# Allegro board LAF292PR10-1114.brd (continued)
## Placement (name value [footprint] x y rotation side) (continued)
PR612  1.91K_0402_1%  [R_0402]  67.17 78.74 0 top
PR613  86.6K_0402_1%  [R_0402]  69.77 78.62 90 top
PR614  0_0402_5%  [R0402_0OHM]  67.18 79.62 0 top
PR615  0_0402_5%  [R_0402]  75.63 81.16 90 bottom
PR616  0_0402_5%  [R0402_0OHM]  67.18 80.5 0 top
PR617  4.3K_0402_1%  [R_0402]  69.94 82.06 270 top
PR618  49.9_0402_1%  [R_0402]  67.19 78.26 0 bottom
PR619  2.2_0603_5%  [R_0603]  88.63 55.37 270 top
PR620  0_0402_5%  [R0402_0OHM]  68.61 82.07 270 bottom
PR621  316_0402_1%  [R_0402]  70.83 82.07 270 top
PR622  1.5K_0402_1%  [R_0402]  71.23 82.07 270 bottom
PR623  2K_0402_1%  [R_0402]  70.35 82.07 270 bottom
PR624  3.65K_0603_1%  [R_0603]  97.72 55.03 0 top
PR625  0_0402_5%  [R0402_0OHM]  67.19 77.38 0 bottom
PR626  10_0402_1%  [R_0402]  67.2 76.51 0 bottom
PR627  4.7_1206_5%  [R_1206]  90.34 54.63 0 top
PR628  4.99K_0402_1%  [R_0402]  99.6 77.51 270 top
PR629  86.6K_0402_1%  [R_0402]  74.45 78.23 0 top
PR630  2.49K_0402_1%  [R_0402]  73.05 72.37 270 top
PR631  27.4K_0402_1%  [R_0402]  68.59 82.92 0 bottom
PR632  1K_0402_1%  [R_0402]  73.57 82.96 180 top
PR633  11K_0402_1%  [R_0402]  72.57 81.17 90 top
PR634  0_0402_5%  [R_0402]  74.74 81.17 90 bottom
PR635  10K_0402_1%  [R_0402]  76.8 79.01 270 bottom
PR636  665_0402_1%  [R_0402]  68.85 72.36 270 bottom
PR638  360_0402_1%  [R_0402]  72.98 82.07 270 bottom
PR639  3.09K_0402_1%  [R_0402]  77.77 77.21 180 bottom
PR640  357_0402_1%  [R_0402]  77 74.13 0 bottom
PR641  1K_0402_1%  [R_0402]  68.11 70.57 0 bottom
PR642  2.61K_0402_1%  [R_0402]  98.25 54.03 0 bottom
PR643  11K_0402_1%  [R_0402]  71.5 71.45 90 bottom
PR644  1K_0402_1%  [R_0402]  77 73.24 0 bottom
PR645  316_0402_1%  [R_0402]  77.67 75.97 180 top
PR646  316_0402_1%  [R_0402]  74.13 72.07 270 bottom
PR647  27.4K_0402_1%  [R_0402]  77.7 79.88 180 bottom
PR648  1.91K_0402_1%  [R_0402]  77.97 76.29 180 bottom
PR649  1.62K_0402_1%  [R_0402]  73.24 72.37 270 bottom
PR650  2K_0402_1%  [R_0402]  76.76 76.85 0 top
PR651  113K_0402_1%  [R_0402]  73.91 72.37 270 top
PR652  2K_0402_1%  [R_0402]  75.02 72.07 270 bottom
PR653  20M_0402_5%  [R_0402]  74.44 74.74 0 top
PR656  11K_0402_1%  [R_0402]  76.77 75.08 0 top
PR657  4.42K_0402_1%  [R_0402]  100.18 62.66 0 top
PR658  20M_0402_5%  [R_0402]  73.31 78.71 90 top
PR659  0_0402_5%  [R0402_0OHM]  86.34 71.55 0 bottom
PR660  3.9_0603_1%  [R_0603]  85.91 74.35 359.6 bottom
PR661  3.65K_0603_1%  [R_0603]  99.01 61.47 90 top
PR663  4.7_1206_5%  [R_1206]  93.06 82.38 180 bottom
PR664  0_0402_5%  [R0402_0OHM]  76.18 71.52 270 bottom
PR665  3.9_0603_1%  [R_0603]  90.3 54.9 90 bottom
PR666  10_0402_1%  [R_0402]  99.61 74.82 90 top
PR667  3.65K_0603_1%  [R_0603]  99.76 78.39 90 top
PR668  100K_0603_1%  [R_0603]  100.98 79.79 270 top
PR669  4.7_1206_5%  [R_1206]  98.37 59.55 180 top
PR670  100K_0402_1%  [R_0402]  100.48 77.51 270 top
PR671  0_0402_5%  [R_0402]  86.23 62.85 0 top
PR672  3.9_0603_1%  [R_0603]  84.99 61.65 90 bottom
PR673  10_0402_1%  [R_0402]  94.04 68.91 90 top
PR674  3.65K_0603_1%  [R_0603]  91.8 70.37 270 top
PR675  100K_0603_1%  [R_0603]  93 68.97 90 top
PR676  4.7_1206_5%  [R_1206]  84.66 70.98 180 bottom
PR677  100K_0402_1%  [R_0402]  93.96 71.29 180 top
PR678  100_0402_1%  [R_0402]  67.18 77.85 0 top
PR679  0_0402_5%  [R0402_0OHM]  85.51 50.98 180 bottom
PR682  -  [SOLDER_PREFORMS_0603]  130.43 69.62 180 top
PR683  -  [SOLDER_PREFORMS_0603]  126.46 74.13 0 top
PR684  -  [SOLDER_PREFORMS_0603]  131.03 74.15 180 top
PR686  10K_0402_1%  [R_0402]  88.99 71.94 180 top
PR687  0_0402_5%  [R0402_0OHM]  86.33 70.67 0 bottom
PR688  1_0603_5%  [R_0603]  84.86 72.73 0 bottom
PR689  10K_0402_1%  [R_0402]  89.57 64.91 270 bottom
PR691  1_0603_5%  [R_0603]  89.73 64.35 180 top
PR692  0_0402_5%  [R_0402]  86.23 61.97 0 top
PR901  0.01_1206_1%  [R_1206_4P-D]  60.01 60.44 270 bottom
PR909  2_0603_1%  [R_0603]  49.76 33.72 0 top
PR910  2_0603_1%  [R_0603]  49.76 34.92 0 top
PR914  4.7_0603_5%  [R_0603]  51.8 37.02 180 top
PR915  4.7_0603_5%  [R_0603]  50.78 40.88 270 top
PR916  1_0805_5%  [R_0805]  63.42 32.21 270 top
PR917  0.005_1206_1%  [R_1206_4P-D]  61.54 56.63 180 top
PR918  100K_0402_1%  [R_0402]  54.19 32.16 90 top
PR919  0_0402_5%  [R_0402]  55.08 32.17 90 top
PR920  0_0402_5%  [R0402_0OHM]  56.13 31.89 90 top
PR921  4.7_0603_5%  [R_0603]  53.84 40.58 90 top
PR922  0_0402_5%  [R0402_0OHM]  57.02 31.89 90 top
PR923  4.7_1206_5%  [R_1206]  54.96 51.67 180 top
PR924  4.7_1206_5%  [R_1206]  65.69 47.85 0 top
PR925  154K_0402_1%  [R_0402]  53.28 30.39 90 top
PR926  0_0402_5%  [R0402_0OHM]  57.9 31.89 90 top
PR927  1M_0402_1%  [R_0402]  49.04 31.3 270 top
PR928  0_0402_5%  [R0402_0OHM]  54.2 31.33 270 top
PR929  0_0402_5%  [R0402_0OHM]  56.13 40.56 90 top
PR930  100K_0402_1%  [R_0402]  58.94 32.13 270 top
PR931  100K_0402_1%  [R_0402]  59.85 33.02 180 top
PR932  105K_0402_1%  [R_0402]  58.91 35.46 0 top
PR933  100K_0402_1%  [R_0402]  59.82 34.56 180 top
PR934  0_0402_5%  [R0402_0OHM]  59.35 36.52 90 top
PR935  0_0402_5%  [R0402_0OHM]  63.11 41.23 180 top
PR936  0_0402_5%  [R0402_0OHM]  58.89 38.57 0 top
PR937  1_0603_1%  [R_0603]  57.54 42.93 90 top
PR938  1_0603_1%  [R_0603]  58.74 42.93 90 top
PR939  0_0402_5%  [R0402_0OHM]  68.84 39.55 180 top
PR940  100_0402_5%  [R_0402]  60.51 41.23 180 top
PR941  0_0402_5%  [R0402_0OHM]  67.92 36.05 0 top
PR942  0_0402_5%  [R0402_0OHM]  65.13 40.22 270 top
PR943  0_0603_5%  [R_0603]  51.5 44.4 270 top
PR944  442K_0402_1%  [R_0402]  52.62 43.92 270 top
PR945  100K_0402_5%  [R_0402]  53.55 43.01 90 top
PR946  0_0402_5%  [R0402_0OHM]  63.16 34.71 270 top
PR947  0_0402_5%  [R0402_0OHM]  63.99 41.13 270 top
PR948  16.5K_0402_1%  [R_0402]  58.89 39.46 0 top
PR950  0_0402_5%  [R_0402]  64.05 34.71 270 top
PR951  0_0402_5%  [R0402_0OHM]  71.71 83.83 180 bottom
PR953  100K_0402_1%  [R_0402]  62.27 33.79 90 top
PR960  0_0402_5%  [R0402_0OHM]  56.72 30.98 180 top
PR961  100K_0402_1%  [R_0402]  66.08 39.31 90 top
PR1201  1M_0402_1%  [R_0402]  52.95 86.45 90 top
PR1202  300K_0402_5%  [R_0402]  41.44 72.98 0 top
PR1203  499K_0402_1%  [R_0402]  52.57 83.65 180 bottom
PR1204  499K_0402_1%  [R_0402]  48.43 75.65 90 top
PR1205  100K_0402_5%  [R_0402]  62.58 81.5 180 top
PR1206  1M_0402_5%  [R_0402]  52.57 87.33 0 bottom
PR1207  100K_0402_5%  [R_0402]  39.67 72.98 0 top
PR1208  0_0402_5%  [R0402_0OHM]  63.52 81.48 0 top
PR1209  49.9K_0402_1%  [R_0402]  57.42 85.57 270 top
PR1210  0_0402_5%  [R0402_0OHM]  61.22 77.78 90 top
PR1211  100K_0402_5%  [R_0402]  50.72 86.7 0 bottom
PR1212  49.9K_0402_1%  [R_0402]  61.12 83.53 90 top
PR1213  100K_0402_5%  [R_0402]  49.5 90.28 180 bottom
PR1214  0_0402_5%  [R0402_0OHM]  60.37 82.58 270 top
PR1215  499K_0402_1%  [R_0402]  45.33 87.08 180 top
PR1216  221K_0402_1%  [R_0402]  44.42 89.75 0 top
PR1217  47K_0402_1%  [R_0402]  47.87 90.76 180 top
PR1218  1.8M_0402_1%  [R_0402]  48.74 85.54 90 bottom
PR1219  0_0402_5%  [R0402_0OHM]  64.46 85.41 270 top
PR1220  100K_0402_5%  [R_0402]  58.58 81.76 0 top
PR1221  0_0402_5%  [R0402_0OHM]  58.46 86.46 180 top
PR1222  0_0402_5%  [R0402_0OHM]  64.48 82.69 90 top
PR1223  0_0402_5%  [R0402_0OHM]  46.96 91.65 0 top
PR1224  100K_0402_5%  [R_0402]  60.21 86.44 180 top
PR1225  200K_0402_1%  [R_0402]  44.42 87.97 0 top
PR1226  0_0402_5%  [R0402_0OHM]  57.51 88.75 180 bottom
PR1227  200K_0402_1%  [R_0402]  45.33 91.53 180 top
PR1228  100K_0402_5%  [R_0402]  55.21 85.18 0 bottom
PR1229  100K_0402_5%  [R_0402]  58.84 88.73 0 bottom
PR1230  0_0402_5%  [R0402_0OHM]  38.67 87.36 270 top
PR1231  10K_0402_5%  [R_0402]  40.41 85.56 0 top
PR1232  0_0402_5%  [R0402_0OHM]  39.56 85.55 180 top
PR1233  0_0402_5%  [R0402_0OHM]  54.48 86.88 90 bottom
PR1234  1M_0402_1%  [R_0402]  40.3 51.77 0 top
PR1235  300K_0402_5%  [R_0402]  43.4 57.17 180 top
PR1236  1M_0402_5%  [R_0402]  41.06 45.47 90 top
PR1237  499K_0402_1%  [R_0402]  41.54 44.33 270 top
PR1238  499K_0402_1%  [R_0402]  49.07 49.23 90 top
PR1239  100K_0402_5%  [R_0402]  38.28 41.28 90 top
PR1240  100K_0402_5%  [R_0402]  44.26 58 270 top
PR1241  0_0402_5%  [R0402_0OHM]  38.33 40.45 270 top
PR1242  100K_0402_5%  [R_0402]  48.23 46.95 0 top
PR1243  0_0402_5%  [R0402_0OHM]  34.81 40.49 90 top
PR1244  49.9K_0402_1%  [R_0402]  42.41 37.11 90 top
PR1245  0_0402_5%  [R0402_0OHM]  42.89 32.95 0 top
PR1246  49.9K_0402_1%  [R_0402]  45.88 36.69 0 top
PR1247  0_0402_5%  [R0402_0OHM]  42.1 32.04 270 top
PR1248  0_0402_5%  [R0402_0OHM]  45.07 34 90 top
PR1249  100K_0402_5%  [R_0402]  49.7 43.02 180 top
PR1250  100K_0402_5%  [R_0402]  43.22 34.88 0 top
PR1251  0_0402_5%  [R0402_0OHM]  37.58 32.98 180 top
PR1252  499K_0402_1%  [R_0402]  33.17 34.08 90 top
PR1253  221K_0402_1%  [R_0402]  39.36 32.98 180 top
PR1254  47K_0402_1%  [R_0402]  36.98 38.71 180 top
PR1255  0_0402_5%  [R0402_0OHM]  43.16 38.88 180 top
PR1256  1.8M_0402_1%  [R_0402]  34.13 39.01 0 top
PR1257  100K_0402_5%  [R_0402]  44.94 38.86 180 top
PR1258  100K_0402_5%  [R_0402]  41.19 31.12 90 top
PR1259  0_0402_5%  [R0402_0OHM]  35.04 37.07 270 top
PR1260  100K_0402_5%  [R_0402]  35.73 31.89 90 top
PR1261  200K_0402_1%  [R_0402]  34.09 35.02 270 top
PR1262  200K_0402_1%  [R_0402]  36.95 34.12 180 top
PR1263  100K_0402_5%  [R_0402]  65.19 83.35 270 bottom
PR1264  100K_0402_5%  [R_0402]  65.24 87.72 0 bottom
PR1265  0_0402_5%  [R0402_0OHM]  34.84 31.89 90 top
PR1266  0_0402_5%  [R0402_0OHM]  43.48 33.49 0 bottom
PR1267  100K_0402_5%  [R_0402]  69.56 86.85 90 bottom
PR1268  100K_0402_5%  [R_0402]  74.8 83.52 180 bottom
PR1269  0_0402_5%  [R0402_0OHM]  43.48 32.6 0 bottom
PR1270  10K_0402_5%  [R_0402]  42.08 33.49 180 bottom
PR1271  100K_0402_5%  [R_0402]  67.15 87.72 0 bottom
PR1272  100K_0402_5%  [R_0402]  74.13 87.59 0 bottom
PR1273  0_0402_5%  [R0402_0OHM]  66.08 82.64 90 bottom
PR1274  0_0402_5%  [R0402_0OHM]  76.37 84.97 90 bottom
PR1275  0_0402_5%  [R0402_0OHM]  64.18 88.55 270 bottom
PR1276  0_0402_5%  [R0402_0OHM]  64.3 82.43 90 bottom
PR1277  300K_0402_5%  [R_0402]  46.02 84.12 270 bottom
PR1278  100K_0402_5%  [R_0402]  38.8 82.31 90 top
PR1279  100K_0402_5%  [R_0402]  46.02 82.37 270 bottom
PR1280  300K_0402_5%  [R_0402]  46.82 42.62 270 top
PR1281  100K_0402_5%  [R_0402]  47.64 34.92 0 top
PR1282  100K_0402_5%  [R_0402]  46.82 40.79 270 top
PR1283  0_0402_5%  [R_0402]  45.59 32.98 180 top
PR1284  0_0402_5%  [R_0402]  66.29 85.43 180 top
PR1285  1M_0402_5%  [R_0402]  42.72 84.29 270 top
PR1286  1M_0402_5%  [R_0402]  41.11 32.98 0 top
PR1287  10K_0402_5%  [R_0402]  51.68 85.81 180 bottom
PR1288  10K_0402_5%  [R_0402]  43.98 37.8 180 bottom
PR1289  0_0402_5%  [R_0402]  69.56 85.02 90 bottom
PR1290  0_0402_5%  [R_0402]  76.57 83.52 180 bottom
PR1291  100K_0402_5%  [R_0402]  72.23 87.72 0 bottom
PR1292  0_0402_5%  [R0402_0OHM]  71.37 87.72 180 bottom
PR1293  0_0402_5%  [R_0402]  69.33 83.92 180 bottom
PR1294  0_0402_5%  [R_0402]  77.39 85.89 270 bottom
PR1295  0_0402_5%  [R0402_0OHM]  47.86 91.3 180 bottom
PR1296  0_0402_5%  [R0402_0OHM]  49.26 42.13 180 top
PR1298  10K_0402_1%  [R_0402]  94.26 57.92 270 bottom
PR1299  0_0402_5%  [R0402_0OHM]  77.06 71.52 270 bottom
PR1300  1_0603_5%  [R_0603]  91.32 64.74 270 top
PRP1  100_0804_8P4R_5%  [RP_0804_8P4R]  67.83 44.07 270 top
PT1  PAD~D  [TPC12]  38.35 84.6 0 top
PT2  PAD~D  [TPC12]  38.33 41.66 180 bottom
PU100  -  [SY8288BRAC_QFN20_3X3]  72.53 43.25 0 bottom
PU102  SYV828CRAC QFN 20P PWM  [SY8288CRAC_QFN20_3X3]  50.69 70.18 0 bottom
PU200  -  [SY8210AQVC_QFN19_4X3]  85.79 44.92 180 bottom
PU301  SY8286RAC_QFN20_3X3  [SY8288RAC_QFN20_3X3]  60.98 71.58 0 bottom
PU401  -  [TPS62134CRGT_QFN16_3X3]  178.86 27.77 180 top
PU402  TPS62134DRGT_QFN16_3X3  [TPS62134ARGT_QFN16_3X3]  165.55 31.1 90 bottom
PU501  -  [RT8097ALGE_SOT23-6]  211.79 28.33 90 top
PU503  AP7361C-FGE-7-01_U-DFN3030-8_3X3  [AP7361C-FGE-7_U-DFN3030-8_3X3]  78.65 51.48 0 top
PU602  ISL95857AHRTZ-T TQFN 40P PWM  [ISL62883CHRTZ-T_TQFN40_5X5-S]  70.49 79 0 bottom
PU610  FDMF3035_PQFN31_5X5  [NCP302045MNTWG_PQFN33_5X5]  88.56 72.24 90 bottom
PU612  FDMF3035_PQFN31_5X5  [NCP302045MNTWG_PQFN33_5X5]  92.31 57.58 180 bottom
PU613  FDMF3035_PQFN31_5X5  [NCP302045MNTWG_PQFN33_5X5]  87.65 64.33 180 bottom
PU614  ISL95808HRZ-TS2378_DFN8_2X2  [ISL95808HRZ-TS2378_DFN8_2X2-S]  89.02 50.95 270 bottom
PU901  ISL9538HRTZ-T TQFN 32P PWM  [ISL88738HRTZ-T_TQFN32_4X4]  56.94 38.59 270 top
PU903  MC74VHC1G08DFT2G SC70 5P AND  [SN74AHC1G08DCKR_SC70-5]  65.36 37.94 180 top
PU1201  -  [LM393DGKR_VSSOP8]  44.87 90.89 180 bottom
PU1202  MC74VHC1G08DFT2G SC70 5P AND  [SN74AHC1G08DCKR_SC70-5]  65.64 84.25 270 top
PU1203  MC74VHC1G08DFT2G SC70 5P AND  [SN74AHC1G08DCKR_SC70-5]  43.25 31.79 270 top
Q1  -  [L2N7002WT1G_SC-70-3]  241.6 74.25 180 top
QC2  -  [DMN65D8LDW-7_SOT363-6]  151.87 76.43 270 top
QC3  S TR BSS138W 1N SOT-323-3  [L2N7002WT1G_SC-70-3]  248.71 86.51 0 top
QC4  DMN63D8LDW-7_SOT363-6  [DMN65D8LDW-7_SOT363-6]  181.64 39.1 180 bottom
QC6  -  [L2N7002WT1G_SC-70-3]  20.24 85.5 0 bottom
QC7  -  [LP2301ALT1G_SOT23-3]  30.29 82.25 90 top
QE2  -  [DMN65D8LDW-7_SOT363-6]  249.95 69.65 0 top
QE3  LMBT3904WT1G SC70-3  [MMBT3904WT1G_SC70-3]  121.27 65.36 270 top
QE4  LMBT3904WT1G SC70-3  [MMBT3904WT1G_SC70-3]  255.31 47.64 180 top
QE5  LMBT3904WT1G SC70-3  [MMBT3904WT1G_SC70-3]  43.48 65.94 180 bottom
QE6  LMBT3904WT1G SC70-3  [MMBT3904WT1G_SC70-3]  80.07 51.25 90 bottom
QE7  LMBT3904WT1G SC70-3  [MMBT3904WT1G_SC70-3]  162.77 38.2 180 bottom
QE11  -  [L2N7002WT1G_SC-70-3]  252.77 47.64 0 top
QE12  -  [L2N7002WT1G_SC-70-3]  263.57 75.9 270 top
QE15  -  [LP2301ALT1G_SOT23-3]  266.87 84.03 90 top
QE17  -  [L2N7002WT1G_SC-70-3]  263.57 78.57 270 top
QR1  -  [L2N7002WT1G_SC-70-3]  277.92 61.81 180 top
QT1  -  [DMN66D0LDW-7_SOT363-6]  38.08 89.73 90 top
QT2  -  [DMN66D0LDW-7_SOT363-6]  26.02 37.44 270 top
QV1  -  [AO6405_TSOP6]  224.41 32.69 270 bottom
QV2  -  [L2N7002WT1G_SC-70-3]  228.01 30.69 270 bottom
QV3  -  [DMN65D8LDW-7_SOT363-6]  17.89 50.98 90 bottom
QV4  -  [L2N7002WT1G_SC-70-3]  14.33 37.78 180 bottom
QV5  -  [L2N7002WT1G_SC-70-3]  33.32 91.97 180 bottom
QV6  -  [L2N7002WT1G_SC-70-3]  14.9 54.63 0 top
QZ1  -  [LP2301ALT1G_SOT23-3]  227.4 34.17 90 bottom
QZ2  -  [DMN65D8LDW-7_SOT363-6]  256.33 87.46 90 top
QZ3  -  [DDTA114EUA-7-F_SOT323-3]  251.59 88.1 270 top
QZ4  -  [L2N7002WT1G_SC-70-3]  250.74 75.2 0 top
QZ10  -  [DMN65D8LDW-7_SOT363-6]  230.8 53.27 180 top
QZ13  -  [DMN65D8LDW-7_SOT363-6]  230.8 50.22 180 top
QZ14  -  [DMN65D8LDW-7_SOT363-6]  226.85 48.28 0 top
QZ15  S TR BSS138W 1N SOT-323-3  [L2N7002WT1G_SC-70-3]  236.58 31.84 270 bottom
RA3  0_0603_5%  [R0603_0OHM]  264.89 28.5 90 top
RA5  2.2K_0402_5%  [R_0402]  273.41 31.89 180 top
RA6  2.2K_0402_5%  [R_0402]  272.52 33.66 270 top
RA7  16.2_0402_1%  [R_0402]  272.5 30.94 0 top
RA8  16.2_0402_1%  [R_0402]  272.5 29.99 0 top
RA9  33_0402_5%  [R_0402]  261.05 32.93 0 top
RA12  1K_0402_5%  [R_0402]  275.1 36.66 0 top
RA13  1K_0402_5%  [R_0402]  275.1 35.77 0 top
RA14  22_0402_5%  [R_0402]  261.05 35.09 0 top
RA17  33_0402_5%  [R_0402]  261.97 34.22 180 top
RA18  10K_0402_5%  [R_0402]  259 40.39 90 top
RA35  0_0402_5%  [R0402_0OHM]  273.73 28.36 270 top
RA36  0_0402_5%  [R0402_0OHM]  275 28.36 270 top
RA37  0_0402_5%  [R0402_0OHM]  276.67 41.82 180 top
RA44  100K_0402_5%  [R_0402]  272.15 40.47 180 top
RA45  10K_0402_5%  [R_0402]  274.92 34.91 270 top
RA48  0_0402_5%  [R0402_0OHM]  257.4 39.46 0 top
RA50  0_0402_5%  [R_0402]  259.89 41.31 270 top
RA51  10K_0402_5%  [R_0402]  276.58 37.63 90 top
RA52  0_0402_5%  [R0402_0OHM]  274.81 30.94 0 top
RA53  0_0402_5%  [R0402_0OHM]  274.81 29.99 0 top
RA54  0_0402_5%  [R_0402]  264.38 41.13 90 top
RA55  0_0402_5%  [R0402_0OHM]  263.43 41.13 90 top
RA58  10K_0402_5%  [R_0402]  296.03 20.41 180 top
RA59  100K_0402_1%  [R_0402]  260.77 42 270 top
RA60  200K_0402_1%  [R_0402]  261.66 41.08 90 top
RA61  100K_0402_5%  [R_0402]  262.54 41.98 270 top
RA62  100K_0402_5%  [R_0402]  261.05 35.89 0 top
RC1  100K_0402_5%  [R_0402]  150.03 75.27 270 top
RC2  24.9_0402_1%  [R_0402]  126.33 78.95 180 top
RC3  100_0402_1%  [R_0402]  149.52 78.77 270 top
RC4  200_0402_1%  [R_0402]  157.31 63.55 180 top
RC5  200_0402_1%  [R_0402]  146.4 62.95 0 top
RC6  80.6_0402_1%  [R_0402]  146.39 54.45 270 top
RC7  162_0402_1%  [R_0402]  147.92 53.12 270 top
RC10  1K_0402_1%  [R_0402]  165.06 91.6 270 top
RC11  1K_0402_1%  [R_0402]  162.14 58.63 180 bottom
RC12  1K_0402_5%  [R_0402]  163.28 74.25 0 top
RC14  1K_0402_5%  [R_0402]  160.9 75.8 0 top
RC15  1K_0402_5%  [R_0402]  162.57 71.33 0 top
RC16  15_0402_5%  [R_0402]  161.84 54.52 270 bottom
RC17  1K_0402_5%  [R_0402]  160.22 70.99 0 top
RC21  8.2K_0402_1%  [R_0402]  162.32 51.9 0 bottom
RC22  22_0402_5%  [R_0402]  163.67 53.93 0 bottom
RC23  2.2K_0402_5%  [R_0402]  155.54 71.26 0 top
RC25  4.7K_0402_5%  [R_0402]  157.32 71.28 270 top
RC27  8.2K_0402_5%  [R_0402]  163.67 52.79 0 bottom
RC28  33_0402_5%  [R_0402]  168.57 52.1 270 bottom
RC29  33_0402_5%  [R_0402]  177.35 60.52 90 top
RC30  1K_0402_5%  [R_0402]  178.48 56.55 270 top
RC31  1K_0402_5%  [R_0402]  176.7 56.55 270 top
RC32  0_0402_5%  [R_0402]  172.44 44.12 180 top
RC33  0_0402_5%  [R0402_0OHM]  172.44 45.2 180 top
RC34  0_0402_5%  [R0402_0OHM]  172.44 46.28 180 top
RC35  0_0402_5%  [R0402_0OHM]  172.44 47.36 180 top
RC36  0_0402_5%  [R0402_0OHM]  172.44 48.34 180 top
RC37  0_0402_5%  [R0402_0OHM]  180.26 59.24 90 bottom
RC38  0_0402_5%  [R0402_0OHM]  172.44 49.29 180 top
RC39  33_0402_5%  [R_0402]  180.26 57.49 90 bottom
RC40  0_0402_5%  [R0402_0OHM]  172.46 50.25 180 top
RC41  0_0402_5%  [R0402_0OHM]  172.43 52.33 270 top
RC42  0_0402_5%  [R_0402]  180.26 55.71 90 bottom
RC43  33_0402_5%  [R_0402]  181.65 54.44 180 bottom
RC44  113_0402_1%  [R_0402]  153.25 70.06 0 top
RC45  100_0402_1%  [R_0402]  153.74 78.02 90 top
RC46  1M_0402_1%  [R_0402]  131.61 90.51 180 bottom
RC47  10K_0402_5%  [R_0402]  158.95 52.56 180 top
RC48  1K_0402_5%  [R_0402]  152.36 51.22 270 bottom
RC50  10K_0201_1%  [R_0201]  151.26 65.57 0 top
RC51  10K_0402_5%  [R_0402]  155.36 62.87 90 top
RC52  2.7K_0402_1%  [R_0402]  142.77 73.87 0 top
RC54  10M_0402_5%  [R_0402]  159.73 62.77 180 top
RC56  20K_0402_5%  [R_0402]  152.62 51.57 90 top
RC57  20K_0402_5%  [R_0402]  154.9 54.44 270 top
RC59  10K_0402_5%  [R_0402]  161 51.93 270 top
RC60  0_0402_5%  [R_0402]  189.03 37.63 180 bottom
RC65  100K_0402_5%  [R_0402]  184.62 36.23 180 bottom
RC67  1K_0402_5%  [R_0402]  154.86 51.22 270 bottom
RC68  10K_0402_5%  [R_0402]  156.63 51.22 270 bottom
RC69  1M_0402_5%  [R_0402]  152.44 54.39 270 top
RC71  1K_0402_5%  [R_0402]  110.46 87.59 0 bottom
RC72  8.2K_0402_5%  [R_0402]  154.01 54.44 270 top
RC73  10K_0402_5%  [R_0402]  155.82 54.44 270 top
RC74  10K_0402_5%  [R_0402]  157.7 47.96 0 top
RC75  10K_0402_5%  [R_0402]  151.47 51.22 270 bottom
RC77  1K_0402_5%  [R_0402]  103.56 84.03 0 bottom
RC78  60.4_0402_1%  [R_0402]  110.53 86.65 270 bottom
RC79  49.9_0402_1%  [R_0402]  118.28 85.86 90 bottom
RC80  1K_0402_5%  [R_0402]  116.5 85.86 90 bottom
RC81  51_0402_5%  [R_0402]  120.57 87.77 90 bottom
RC82  100_0402_5%  [R_0402]  122.52 85.86 90 bottom
RC83  1K_0402_5%  [R_0402]  105.55 85.91 90 bottom
RC84  499_0402_1%  [R_0402]  106.44 86.83 270 bottom
RC86  51_0402_5%  [R_0402]  121.58 85.86 90 bottom
RC87  1K_0402_5%  [R_0402]  118.79 87.77 90 bottom
RC88  49.9_0402_1%  [R_0402]  149.06 53.12 270 top
RC89  49.9_0402_1%  [R_0402]  149.95 53.12 270 top
RC90  49.9_0402_1%  [R_0402]  117.34 76.8 180 top
RC91  49.9_0402_1%  [R_0402]  117.34 75.92 180 top
RC92  33_0402_5%  [R_0402]  146.6 52.03 90 bottom
RC93  33_0402_5%  [R_0402]  145.71 50 90 bottom
RC94  33_0402_5%  [R_0402]  149.27 50.25 180 top
RC95  33_0402_5%  [R_0402]  144.82 50 90 bottom
RC96  200_0402_1%  [R_0402]  152.11 70.82 180 top
RC109  1K_0402_5%  [R_0402]  103.75 82.24 270 bottom
RC110  10K_0402_1%  [R_0402]  102.77 86.63 180 bottom
RC112  10K_0402_1%  [R_0402]  106.23 84.17 180 bottom
RC113  10K_0402_1%  [R_0402]  104.69 85.94 180 bottom
RC114  49.9_0402_1%  [R_0402]  121.89 78.22 180 top
RC115  1.5K_0402_5%  [R_0402]  63.16 87.64 90 bottom
RC120  100K_0402_5%  [R_0402]  111.4 85.79 90 bottom
RC121  0_0402_5%  [R_0402]  71.72 92.08 270 bottom
RC122  0_0402_5%  [R_0402]  70.83 92.08 270 bottom
RC123  1K_0402_5%  [R_0402]  67.91 91.17 90 bottom
RC124  1K_0402_5%  [R_0402]  67.02 91.17 90 bottom
RC126  1K_0402_5%  [R_0402]  73.7 91.11 180 bottom
RC128  0_0402_5%  [R_0402]  60.29 91.1 90 bottom
RC129  0_0402_5%  [R_0402]  61.24 91.1 90 bottom
RC130  51_0402_5%  [R_0402]  119.68 87.77 90 bottom
RC131  51_0402_5%  [R_0402]  84.29 90.64 0 top
RC132  150_0402_5%  [R_0402]  72.79 92 0 bottom
RC133  1.5K_0402_5%  [R_0402]  59.34 91.1 90 bottom
RC134  51_0402_5%  [R_0402]  86.38 89.46 0 top
RC135  100_0402_5%  [R_0402]  86.38 87.56 0 top
RC136  51_0402_5%  [R_0402]  80.5 87.69 180 top
RC137  3K_0402_5%  [R_0402]  62.32 86.49 270 top
RC138  51_0402_5%  [R_0402]  75.21 91.95 270 bottom
RC139  51_0402_5%  [R_0402]  58.39 91.1 90 bottom
RC140  100_0402_1%  [R_0402]  139.15 85.43 90 bottom
RC141  100_0402_1%  [R_0402]  138.27 85.43 90 bottom
RC143  0_0603_5%  [R0603_0OHM]  135.89 87.61 180 top
RC152  56_0402_1%  [R_0402]  113.17 85.79 90 bottom
RC153  220_0402_5%  [R_0402]  114.06 85.79 90 bottom
RC157  100_0402_1%  [R_0402]  112.29 85.79 90 bottom
RC161  100_0402_1%  [R_0402]  114.39 76.46 90 top
RC163  100_0402_1%  [R_0402]  115.28 76.46 90 top
RC165  100_0402_1%  [R_0402]  141.18 65.48 180 top
RC166  100_0402_1%  [R_0402]  144.74 77.76 90 top
RC167  100_0402_1%  [R_0402]  142.04 65.33 90 top
RC168  100_0402_1%  [R_0402]  145.71 78.7 270 top
RC169  0_0603_5%  [R0603_0OHM]  153.5 87.7 180 top
RC170  0_0402_5%  [R0402_0OHM]  147.67 88.49 270 top
RC171  0_0402_5%  [R0402_0OHM]  137.88 88.32 270 top
RC173  0_0402_5%  [R0402_0OHM]  143.43 88.34 270 top
RC175  2.2K_0402_5%  [R_0402]  156.81 73.22 180 top
RC176  2.2K_0402_5%  [R_0402]  154.84 74.99 0 top
RC177  2.2K_0402_5%  [R_0402]  154.84 74.11 0 top
RC178  2.2K_0402_5%  [R_0402]  156.81 72.33 180 top
RC183  8.2K_0402_5%  [R_0402]  158.92 50.71 270 top
RC184  8.2K_0402_5%  [R_0402]  154.49 64.6 0 top
RC186  4.7K_0402_5%  [R_0402]  157.65 54.44 270 top
RC187  4.7K_0402_5%  [R_0402]  157.65 47.08 0 top
RC189  10K_0402_5%  [R_0402]  156.76 54.44 270 top
RC190  10K_0402_5%  [R_0402]  154.47 62.87 90 top
RC211  0_0402_5%  [R_0402]  173.83 63.15 270 top
RC212  0_0402_5%  [R_0402]  174.71 63.15 270 top
RC214  0_0402_5%  [R_0402]  155.16 47.71 0 top
RC215  0_0402_5%  [R_0402]  150.58 51.22 270 bottom
RC216  0_0603_5%  [R0603_0OHM]  66.4 89.62 180 bottom
RC217  0_0402_5%  [R_0402]  73.7 90.16 180 bottom
RC218  150_0402_5%  [R_0402]  73.7 89.21 180 bottom
RC219  10K_0402_5%  [R_0402]  75.21 90.11 270 bottom
RC220  100K_0402_1%  [R_0402]  148.81 51.22 270 bottom
RC221  0_0402_5%  [R0402_0OHM]  209.42 33.87 180 top
RC222  1K_0402_5%  [R_0402]  205.78 35.65 90 bottom
RC223  1K_0402_5%  [R_0402]  158.54 46.19 180 top
RC224  1K_0402_5%  [R_0402]  171.92 77.21 180 bottom
RC225  8.2K_0402_5%  [R_0402]  176.53 76.83 0 bottom
RC227  8.2K_0402_5%  [R_0402]  176.53 77.72 0 bottom
RC228  0_0402_5%  [R0402_0OHM]  80.5 89.59 180 top
RC229  0_0402_5%  [R0402_0OHM]  86.38 88.51 0 top
RC230  0_0402_5%  [R0402_0OHM]  86.38 86.61 0 top
RC231  0_0402_5%  [R0402_0OHM]  135.95 65.68 0 top
RC234  0_0402_5%  [R_0402]  157.19 69.3 0 top
RC235  0_0402_5%  [R0402_0OHM]  157.19 68.41 0 top
RC237  10K_0402_5%  [R_0402]  152.62 64.65 90 top
RC239  0_0402_5%  [R_0402]  69.82 91.17 90 bottom
RC240  0_0402_5%  [R_0402]  68.93 91.17 90 bottom
RC241  1.5K_0402_5%  [R_0402]  65.26 92.07 180 bottom
RC243  10K_0402_5%  [R_0402]  153.97 51.22 270 bottom
RC244  0_0402_5%  [R0402_0OHM]  188.89 36.23 0 bottom
RC267  10K_0402_5%  [R_0402]  158.54 54.44 270 top
RC268  10K_0402_5%  [R_0402]  159.43 54.44 270 top
RC272  10K_0402_5%  [R_0402]  166.97 87.46 90 top
RC278  10K_0402_5%  [R_0402]  162.9 66.89 0 top
RC279  10K_0402_5%  [R_0402]  174.74 65.11 180 top
RC282  100K_0402_5%  [R_0402]  153.41 64.65 90 top
RC283  10K_0402_5%  [R_0402]  166.21 65.82 270 bottom
RC287  100K_0402_5%  [R_0402]  173.53 39.33 270 top
RC288  10K_0402_5%  [R_0402]  166.08 87.46 90 top
RC290  0_0402_5%  [R0402_0OHM]  176.53 78.67 0 bottom
RC291  10K_0402_5%  [R_0402]  171 78.17 0 bottom
RC292  10K_0402_5%  [R_0402]  163.08 64.6 0 bottom
RC296  0_0402_5%  [R0402_0OHM]  160.58 62.79 0 top
RC297  0_0402_5%  [R_0402]  115.15 88.54 90 top
RC298  0_0402_5%  [R_0402]  116.1 88.54 90 top
RC299  0_0603_5%  [R0603_0OHM]  154.98 77.49 270 top
RC300  0_0402_5%  [R0402_0OHM]  159.12 78.1 90 top
RC301  0_0402_5%  [R0402_0OHM]  158.59 74.13 180 top
RC302  0_0402_5%  [R0402_0OHM]  157.37 78.01 90 top
RC303  0_0402_5%  [R0402_0OHM]  137.01 88.32 270 top
RC304  0_0402_5%  [R0402_0OHM]  155.16 70.19 270 top
RC305  0_0402_5%  [R0402_0OHM]  163.49 67.78 180 top
RC306  0_0402_5%  [R0402_0OHM]  163.49 69.55 180 top
RC307  0_0402_5%  [R0402_0OHM]  163.49 68.67 180 top
RC308  0_0402_5%  [R0402_0OHM]  163.49 70.44 180 top
RC309  0_0603_5%  [R0603_0OHM]  157.57 89.05 270 top
RC310  0_0603_5%  [R0603_0OHM]  154.58 89.05 270 top
RC311  10K_0402_5%  [R_0402]  151.09 54.39 270 top
RC313  0_0402_5%  [R_0402]  152.46 71.9 180 top
RC316  1K_0402_5%  [R_0402]  177.59 56.55 270 top
RC317  150K_0402_5%  [R_0402]  157.19 64.6 180 top
RC318  2.2K_0402_5%  [R_0402]  160.9 76.69 0 top
RC319  2.2K_0402_5%  [R_0402]  160.9 74.79 0 top
RC323  10K_0402_5%  [R_0402]  156.13 48.73 180 top
RC324  59_0402_1%  [R_0402]  142.78 72.52 270 top
RC325  0_0402_5%  [R0402_0OHM]  185.74 34.38 270 bottom
RC328  0_0402_5%  [R0402_0OHM]  119.17 86.78 270 bottom
RC330  49.9K_0402_1%  [R_0402]  160.24 67.01 0 top
RC331  49.9K_0402_1%  [R_0402]  160.24 67.79 0 top
RC337  0_0402_5%  [R0402_0OHM]  155.08 67.27 0 top
RC338  1K_0402_5%  [R_0402]  155.08 68.24 0 top
RC344  10K_0402_5%  [R_0402]  155.74 51.22 270 bottom
RC345  100K_0402_5%  [R_0402]  167.86 87.46 90 top
RC346  10K_0402_5%  [R_0402]  162.01 87.59 90 top
RC347  499_0402_1%  [R_0402]  159.97 78.61 0 top
RC348  499_0402_1%  [R_0402]  160.23 70.21 0 top
RC349  10K_0402_5%  [R_0402]  163.03 58.63 0 bottom
RC358  2.2K_0402_5%  [R_0402]  162.57 74.63 0 bottom
RC359  2.2K_0402_5%  [R_0402]  162.57 73.75 0 bottom
RC360  1K_0402_5%  [R_0402]  162.57 72.86 0 bottom
RC361  1K_0402_5%  [R_0402]  163.84 71.97 0 bottom
RC362  1K_0402_5%  [R_0402]  164.43 69.5 270 top
RC363  1K_0402_5%  [R_0402]  165.4 68.59 90 top
RC364  10K_0402_5%  [R_0402]  162.95 55.76 0 bottom
RC365  10K_0402_5%  [R_0402]  163.67 54.82 0 bottom
RC366  15_0402_5%  [R_0402]  158.41 51.22 270 bottom
RC367  15_0402_5%  [R_0402]  162.4 50.12 0 bottom
RC368  15_0402_5%  [R_0402]  158.41 52.99 270 bottom
RC369  15_0402_5%  [R_0402]  162.32 51.01 0 bottom
RC370  10K_0402_5%  [R_0402]  164.69 51.9 0 bottom
RC371  10K_0402_5%  [R_0402]  165.32 73.11 270 top
RC372  10K_0402_5%  [R_0402]  162.57 73.11 0 top
RC373  0_0402_5%  [R0402_0OHM]  230.07 74.1 90 top
RC374  0_0402_5%  [R0402_0OHM]  158.95 51.67 180 top
RC376  0_0402_5%  [R0402_0OHM]  162.01 51.93 270 top
RC378  0_0402_5%  [R0402_0OHM]  175.68 62.24 90 top
RC387  100K_0201_5%  [R_0201]  150.59 66.19 90 top
RC388  10K_0402_5%  [R_0402]  164.07 60.77 180 bottom
RC389  10K_0402_5%  [R_0402]  164.07 59.86 180 bottom
RC390  10K_0402_5%  [R_0402]  164.07 61.68 180 bottom
RC391  10K_0402_5%  [R_0402]  163.99 63.58 180 bottom
RC392  10K_0402_5%  [R_0402]  163.99 62.63 180 bottom
RC393  10K_0402_5%  [R_0402]  161.23 60.66 0 bottom
RC394  10K_0402_5%  [R_0402]  161.23 59.65 0 bottom
RC395  10K_0402_5%  [R_0402]  161.23 61.68 0 bottom
RC396  10K_0402_5%  [R_0402]  161.23 63.68 0 bottom
RC397  10K_0402_5%  [R_0402]  161.23 62.73 0 bottom
RC400  10K_0402_5%  [R_0402]  160.22 71.78 0 top
RC401  10K_0402_5%  [R_0402]  160.22 72.56 0 top
RC402  49.9K_0402_1%  [R_0402]  159.22 67.98 270 top
RC403  49.9K_0402_1%  [R_0402]  164.35 65.49 0 bottom
RC407  33_0402_5%  [R_0402]  169.54 54.06 180 bottom
RC408  33_0402_5%  [R_0402]  167.68 51.19 90 bottom
RC409  33_0402_5%  [R_0402]  170.35 51.19 90 bottom
RC410  33_0402_5%  [R_0402]  174.51 55.58 0 top
RC411  10K_0402_5%  [R_0402]  147.92 51.22 270 bottom
RC415  1M_0402_1%  [R_0402]  143.68 90.69 90 bottom
RC417  33_0402_5%  [R_0402]  144.57 90.69 90 bottom
RC418  33_0402_5%  [R_0402]  144.65 89.75 180 bottom
RC419  0_0402_5%  [R_0402]  131.61 89.62 180 bottom
RC420  0_0402_5%  [R_0402]  133.37 89.29 180 bottom
RC431  100K_0402_5%  [R_0402]  18.46 87.41 270 bottom
RC432  499K_0402_1%  [R_0402]  25.49 82.76 0 top
RC433  49.9K_0402_1%  [R_0402]  26.41 83.65 180 top
RC436  0_0402_5%  [R_0402]  117.82 78.95 0 top
RC437  0_0402_5%  [R_0402]  128.82 87.59 180 top
RC438  0_0402_5%  [R_0402]  122.72 67.14 90 top
RC439  0_0402_5%  [R0402_0OHM]  37.58 82.25 180 top
RC440  0_0402_5%  [R_0402]  37.58 83.14 180 top
RC441  0_0402_5%  [R0402_0OHM]  168.65 36.53 180 top
RC442  0_0402_5%  [R_0402]  168.39 35.52 180 top
RC443  0_0402_5%  [R_0402]  161.75 45.13 90 top
RC444  0_0402_5%  [R_0402]  157.7 48.85 0 top
RC445  0_0402_5%  [R0402_0OHM]  169.36 37.85 90 top
RC501  10K_0402_5%  [R_0402]  163.03 57.74 0 bottom
RC502  10K_0402_5%  [R_0402]  162.95 56.65 0 bottom
RC503  10K_0402_5%  [R_0402]  170.6 51.11 0 top
RC504  0_0402_5%  [R0402_0OHM]  248.68 79.59 0 top
RC505  0_0402_5%  [R0402_0OHM]  248.68 81.44 0 top
RC506  10K_0402_5%  [R_0402]  249.6 83.52 180 top
RC507  100K_0402_5%  [R_0402]  246.99 84.4 90 top
RC508  0_0402_5%  [R_0402]  250.42 85.82 270 top
RC509  10K_0402_5%  [R_0402]  165 61.67 0 bottom
RC510  2.2K_0402_5%  [R_0402]  179.19 41.5 270 bottom
RC511  2.2K_0402_5%  [R_0402]  181.04 42.01 180 bottom
RC512  2.2K_0402_5%  [R_0402]  182.97 40 90 bottom
RC513  2.2K_0402_5%  [R_0402]  178.33 39.62 0 bottom
RC550  1K_0402_5%  [R_0402]  176.18 61.03 270 top
RC551  10K_0402_5%  [R_0402]  168.83 87.51 90 top
RC552  10K_0402_5%  [R_0402]  272.25 63.2 0 bottom
RC553  10K_0402_5%  [R_0402]  168.34 62.23 180 bottom
RC554  10K_0402_5%  [R_0402]  168.36 61.46 180 bottom
RC555  10K_0402_5%  [R_0402]  168.34 63.01 180 bottom
RC556  10K_0402_5%  [R_0402]  169.09 63.13 90 bottom
RC557  100K_0402_5%  [R_0402]  161.09 69.47 270 top
RC558  100K_0402_5%  [R_0402]  160.29 69.47 270 top
RC559  10K_0402_5%  [R_0402]  39.26 70.7 90 top
RC560  0_0201_5%  [R0201_0OHM]  151.26 64.35 270 top
RC561  0_0201_5%  [R_0201]  151.27 64.97 0 top
RD1  68_0402_1%  [R_0402]  96.42 31.98 90 bottom
RD2  68_0402_1%  [R_0402]  97.37 31.98 90 bottom
RD3  68_0402_1%  [R_0402]  99.28 31.98 90 bottom
RD4  68_0402_1%  [R_0402]  98.33 31.98 90 bottom
RD5  68_0402_1%  [R_0402]  100.23 31.98 90 bottom
RD6  68_0402_1%  [R_0402]  104.99 31.98 90 bottom
RD7  68_0402_1%  [R_0402]  106.9 31.98 90 bottom
RD8  68_0402_1%  [R_0402]  105.95 31.98 90 bottom
RD9  68_0402_1%  [R_0402]  107.85 31.98 90 bottom
RD10  68_0402_1%  [R_0402]  108.8 31.98 90 bottom
RD11  68_0402_1%  [R_0402]  114.52 31.98 90 bottom
RD12  68_0402_1%  [R_0402]  115.47 31.98 90 bottom
RD13  68_0402_1%  [R_0402]  117.38 31.98 90 bottom
RD14  68_0402_1%  [R_0402]  116.42 31.98 90 bottom
RD15  68_0402_1%  [R_0402]  118.33 31.98 90 bottom
RD16  68_0402_1%  [R_0402]  123.09 31.98 90 bottom
RD17  68_0402_1%  [R_0402]  125 31.98 90 bottom
RD18  68_0402_1%  [R_0402]  124.04 31.98 90 bottom
RD19  68_0402_1%  [R_0402]  125.95 31.98 90 bottom
RD20  68_0402_1%  [R_0402]  126.9 31.98 90 bottom
RD21  80.6_0402_1%  [R_0402]  111.66 32.9 270 bottom
RD22  80.6_0402_1%  [R_0402]  112.61 32.9 270 bottom
RD23  80.6_0402_1%  [R_0402]  113.57 32.9 270 bottom
RD24  80.6_0402_1%  [R_0402]  102.14 32.9 270 bottom
RD25  80.6_0402_1%  [R_0402]  101.18 32.9 270 bottom
RD26  37.4_0402_1%  [R_0402]  103.09 32.9 270 bottom
RD27  37.4_0402_1%  [R_0402]  104.04 32.9 270 bottom
RD28  243_0402_1%  [R_0402]  109.76 32.9 270 bottom
RD29  243_0402_1%  [R_0402]  110.71 32.9 270 bottom
RD30  37.4_0402_1%  [R_0402]  122.14 32.9 270 bottom
RD31  243_0402_1%  [R_0402]  125.7 37.17 0 bottom
RD32  243_0402_1%  [R_0402]  125.7 38.19 0 bottom
RD33  37.4_0402_1%  [R_0402]  121.19 32.9 270 bottom
RD34  8.2K_0402_1%  [R_0402]  92.42 44.4 0 bottom
RD35  8.2K_0402_1%  [R_0402]  91.99 43.47 270 bottom
RD36  5.11_0402_1%  [R_0402]  92.41 45.33 0 bottom
RD37  10_0402_1%  [R_0402]  91.36 40.65 90 bottom
RD38  8.2K_0402_1%  [R_0402]  93.32 46.22 180 bottom
RD39  8.2K_0402_1%  [R_0402]  93.32 42.24 90 bottom
RD40  24.9_0402_1%  [R_0402]  90.63 46.28 0 bottom
RD41  24.9_0402_1%  [R_0402]  90.47 42.55 90 bottom
RD42  68_0402_1%  [R_0402]  128.74 31.92 90 bottom
RD43  68_0402_1%  [R_0402]  129.63 31.92 90 bottom
RD44  68_0402_1%  [R_0402]  131.41 31.92 90 bottom
RD45  68_0402_1%  [R_0402]  130.52 31.92 90 bottom
RD46  68_0402_1%  [R_0402]  132.3 31.92 90 bottom
RD47  68_0402_1%  [R_0402]  136.74 31.92 90 bottom
RD48  68_0402_1%  [R_0402]  137.63 31.92 90 bottom
RD49  68_0402_1%  [R_0402]  138.52 31.92 90 bottom
RD50  68_0402_1%  [R_0402]  139.41 31.92 90 bottom
RD51  68_0402_1%  [R_0402]  140.3 31.92 90 bottom
RD52  68_0402_1%  [R_0402]  145.95 31.92 90 bottom
RD53  68_0402_1%  [R_0402]  146.84 31.92 90 bottom
RD54  68_0402_1%  [R_0402]  148.62 31.92 90 bottom
RD55  68_0402_1%  [R_0402]  147.73 31.92 90 bottom
RD56  68_0402_1%  [R_0402]  149.51 31.92 90 bottom
RD57  68_0402_1%  [R_0402]  154.84 31.92 90 bottom
RD58  68_0402_1%  [R_0402]  156.62 31.92 90 bottom
RD59  68_0402_1%  [R_0402]  155.73 31.92 90 bottom
RD60  68_0402_1%  [R_0402]  157.51 31.92 90 bottom
RD61  68_0402_1%  [R_0402]  158.4 31.92 90 bottom
RD62  80.6_0402_1%  [R_0402]  144.1 32.82 0 bottom
RD63  80.6_0402_1%  [R_0402]  143.84 31.93 0 bottom
RD64  80.6_0402_1%  [R_0402]  142.97 32.83 270 bottom
RD65  80.6_0402_1%  [R_0402]  134.08 32.83 270 bottom
RD66  80.6_0402_1%  [R_0402]  133.19 32.83 270 bottom
RD67  37.4_0402_1%  [R_0402]  135.86 32.83 270 bottom
RD68  37.4_0402_1%  [R_0402]  134.97 32.83 270 bottom
RD69  37.4_0402_1%  [R_0402]  153.06 32.83 270 bottom
RD70  243_0402_1%  [R_0402]  141.19 32.83 270 bottom
RD71  243_0402_1%  [R_0402]  142.08 32.83 270 bottom
RD72  243_0402_1%  [R_0402]  159.15 36.58 270 bottom
RD73  243_0402_1%  [R_0402]  159.15 37.51 90 bottom
RD74  37.4_0402_1%  [R_0402]  153.95 32.83 270 bottom
RD75  8.2K_0402_1%  [R_0402]  110.12 51.39 0 bottom
RD76  10_0402_1%  [R_0402]  111.98 51.7 90 bottom
RD77  8.2K_0402_1%  [R_0402]  111.04 52.28 180 bottom
RD78  24.9_0402_1%  [R_0402]  111.04 53.3 180 bottom
RD79  80.6_0402_1%  [R_0402]  120.23 32.9 270 bottom
RD80  80.6_0402_1%  [R_0402]  119.28 32.9 270 bottom
RD81  80.6_0402_1%  [R_0402]  152.16 32.83 270 bottom
RD82  80.6_0402_1%  [R_0402]  151.27 32.83 270 bottom
RD83  100K_0402_5%  [R_0402]  96.19 47.9 90 top
RE5  10K_0402_5%  [R_0402]  271.24 61.43 0 top
RE8  100K_0402_5%  [R_0402]  257.97 66.84 90 top
RE10  100K_0402_5%  [R_0402]  271.24 66.89 0 top
RE11  100K_0402_5%  [R_0402]  252.84 66.03 180 top
RE12  100K_0402_5%  [R_0402]  244.31 77.94 0 top
RE20  100K_0402_5%  [R_0402]  252.9 63.97 180 top
RE21  10K_0402_5%  [R_0402]  264.2 73.84 180 top
RE25  100K_0402_5%  [R_0402]  267.5 52.79 270 top
RE26  10_0402_5%  [R_0402]  267.55 49.51 90 top
RE30  0_0402_5%  [R0402_0OHM]  240.69 32.89 270 bottom
RE31  100K_0402_5%  [R_0402]  246.49 75.29 270 top
RE32  0_0402_5%  [R0402_0OHM]  252.76 67.73 90 top
RE33  10K_0402_5%  [R_0402]  245.53 74.38 90 top
RE35  10K_0402_5%  [R_0402]  271.37 53.68 0 top
RE37  2.2K_0402_5%  [R_0402]  258.98 52.77 270 top
RE38  10K_0402_5%  [R_0402]  271.37 54.57 0 top
RE43  2.2K_0402_5%  [R_0402]  258.08 52.76 270 top
RE48  10K_0402_5%  [R_0402]  165.32 70.44 90 top
RE51  10K_0402_5%  [R_0402]  165.4 66.81 90 top
RE55  100K_0402_5%  [R_0402]  255.31 66.25 180 top
RE56  10K_0402_5%  [R_0402]  252.52 61.85 180 top
RE57  1K_0402_5%  [R_0402]  249.47 65.11 0 top
RE58  100K_0402_5%  [R_0402]  249.47 66 0 top
RE59  0_0402_5%  [R0402_0OHM]  268.65 46.11 90 top
RE60  43_0402_5%  [R_0402]  273.14 55.38 270 top
RE63  100K_0402_5%  [R_0402]  277.79 66.3 90 top
RE64  300_0402_5%  [R_0402]  255.57 51.98 270 top
RE65  100_0402_1%  [R_0402]  276.9 66.3 90 top
RE67  10K_0402_5%  [R_0402]  252.38 69.58 90 top
RE68  100K_0402_5%  [R_0402]  252.82 74.17 270 top
RE69  8.2K_0402_5%  [R_0402]  257.97 47.69 270 top
RE70  2.2K_0402_5%  [R_0402]  253.33 43.48 90 top
RE71  10_0402_1%  [R_0402]  248.46 29.8 180 bottom
RE72  10K_0402_5%  [R_0402]  246.04 31.96 180 bottom
RE73  10K_0402_5%  [R_0402]  242.47 32.89 270 bottom
RE74  10K_0402_5%  [R_0402]  241.58 32.89 270 bottom
RE75  100K_0402_5%  [R_0402]  246.04 32.85 180 bottom
RE77  1.58K_0402_1%  [R_0402]  273.09 64.35 90 top
RE79  4.3K_0402_5%  [R_0402]  272.2 57.97 180 top
RE83  100K_0402_5%  [R_0402]  267.76 47.02 270 top
RE84  100K_0402_5%  [R_0402]  271.23 65.91 0 top
RE85  100K_0402_5%  [R_0402]  271.23 64.95 0 top
RE86  10K_0402_5%  [R_0402]  244.25 31.98 90 bottom
RE90  0_0402_5%  [R0402_0OHM]  252.31 44.39 270 top
RE91  100K_0402_5%  [R_0402]  261.28 70.44 270 top
RE92  100K_0402_5%  [R_0402]  258.92 66.84 90 top
RE93  100K_0201_5%  [R_0201]  261.46 66.72 90 top
RE94  75_0402_5%  [R_0402]  259 71.33 180 top
RE95  100K_0402_5%  [R_0402]  254.25 61.85 180 top
RE274  0_0402_5%  [R_0402]  270.12 48.47 180 top
RE275  0_0402_5%  [R0402_0OHM]  269.41 49.41 90 top
RE280  0_0402_5%  [R_0402]  255.82 74.38 0 top
RE288  100_0402_5%  [R_0402]  271.29 58.86 0 top
RE290  0_0402_5%  [R0402_0OHM]  257.03 67.24 180 top
RE292  0_0402_5%  [R_0402]  257.98 73.62 270 top
RE300  130K_0402_5%  [R_0402]  268.51 51.92 90 top
RE301  10K_0402_5%  [R_0402]  271.24 63.46 0 top
RE302  2.2K_0402_5%  [R_0402]  253.28 71.84 180 top
RE303  2.2K_0402_5%  [R_0402]  251.88 68.67 270 top
RE304  0_0402_5%  [R_0402]  260.52 73.84 180 top
RE306  0_0402_5%  [R_0402]  243.36 32.89 270 bottom
RE308  0_0402_5%  [R_0402]  265.93 46.11 90 top
RE312  300_0402_5%  [R_0402]  256.19 43.48 90 top
RE313  10K_0402_5%  [R_0402]  255.24 43.48 90 top
RE314  100_0402_1%  [R_0402]  254.98 58.91 0 top
RE318  0_0402_5%  [R0402_0OHM]  254.25 60.03 180 top
RE324  100K_0402_5%  [R_0402]  252.93 62.95 180 top
RE340  10K_0402_5%  [R_0402]  255.06 55.79 270 top
RE342  10K_0402_5%  [R_0402]  253.18 41.23 180 top
RE343  33K_0402_5%  [R_0402]  254.25 60.92 180 top
RE349  43K_0402_1%  [R_0402]  260.82 51.86 90 top
RE350  33_0402_5%  [R_0402]  253.53 57.29 90 top
RE362  100K_0402_5%  [R_0402]  255.06 64.73 180 top
RE365  100K_0402_5%  [R_0402]  271.24 62.44 0 top
RE375  0_0402_5%  [R_0402]  196.05 32.47 0 top
RE500  10K_0402_5%  [R_0402]  260.29 78.51 90 top
RE501  10K_0402_5%  [R_0402]  260.01 80.48 90 top
RE502  10K_0402_5%  [R_0402]  260.63 83.38 270 top
RE503  10K_0402_5%  [R_0402]  259.75 82.47 90 top
RE504  10K_0402_5%  [R_0402]  252.3 81.34 270 top
RE505  100K_0402_5%  [R_0402]  255.06 63.84 180 top
RE506  0_0402_5%  [R0402_0OHM]  253.92 62.95 0 bottom
RE507  100K_0402_5%  [R_0402]  260.72 66.84 90 top
RE508  100K_0402_5%  [R_0402]  259.83 66.84 90 top
RE509  0_0402_5%  [R_0402]  272.2 59.9 180 top
RE516  0_0402_5%  [R_0402]  248.12 72.09 180 top
RE517  0_0402_5%  [R_0402]  248.12 71.21 180 top
RE518  0_0402_5%  [R_0402]  252.98 76.67 180 top
RE519  10K_0402_5%  [R_0402]  257.27 50.49 270 top
RE520  10K_0402_5%  [R_0402]  263.06 45.25 270 top
RE521  10K_0402_5%  [R_0402]  235.45 61.81 180 top
RE526  10K_0402_5%  [R_0402]  194.02 35.14 0 top
RE527  10K_0402_5%  [R_0402]  258.86 83.38 270 top
RE528  10K_0402_5%  [R_0402]  257.97 82.47 90 top
RE529  10K_0402_5%  [R_0402]  255.95 55.79 270 top
RE532  4.7K_0402_5%  [R_0402]  195.74 38.9 270 bottom
RE536  0_0402_5%  [R0402_0OHM]  272.03 70.32 180 top
RE539  100_0402_5%  [R_0402]  260.39 47.74 270 top
RE541  100K_0402_5%  [R_0402]  260.9 80.27 90 top
RE543  1M_0402_5%  [R_0402]  263.91 80.49 90 top
RE546  10K_0402_5%  [R_0402]  266.39 81.37 180 top
RE548  0_0402_5%  [R0402_0OHM]  256.13 62.57 0 top
RE550  0_0402_5%  [R_0402]  252.98 77.56 180 top
RE551  0_0402_5%  [R_0402]  266.87 47.02 270 top
RE552  0_0402_5%  [R0402_0OHM]  265.03 46.12 90 top
RE553  1M_0402_5%  [R_0402]  261.42 47.66 270 top
RE554  1M_0402_5%  [R_0402]  256.84 54.87 90 top
RE555  10K_0402_5%  [R_0402]  243.76 61.63 270 top
RE557  100K_0402_5%  [R_0402]  259.88 52.79 270 top
RE560  0_0402_5%  [R_0402]  198.21 33.36 0 top
RE561  100K_0402_5%  [R_0402]  258.87 46.74 90 top
RE562  2.2K_0402_5%  [R_0402]  266.63 51.88 90 top
RE565  0_0402_5%  [R0402_0OHM]  264.7 81.4 270 top
RE600  0_0402_5%  [R0402_0OHM]  58.62 87.91 0 bottom
RE601  0_0402_5%  [R0402_0OHM]  250.27 25.96 0 bottom
RE602  0_0402_5%  [R0402_0OHM]  63.45 82.35 270 bottom
RE603  0_0402_5%  [R0402_0OHM]  241.5 66.73 90 top
RI13  10K_0402_5%  [R_0402]  267.12 73.78 180 top
RI14  22.1K_0402_1%  [R_0402]  271.38 77.02 180 top
RI27  0_0402_5%  [R_0402-NPM]  226.08 80.7 0 top
RI28  0_0402_5%  [R_0402-NPM]  226.08 79.75 0 top
RI29  0_0402_5%  [R_0402-NPM]  226.08 78.8 0 top
RI30  0_0402_5%  [R_0402-NPM]  226.08 77.84 0 top
RI47  0_0402_5%  [R_0402-NPM]  226.39 87.56 0 top
RI48  0_0402_5%  [R_0402-NPM]  226.39 86.61 0 top
RI49  0_0402_5%  [R_0402-NPM]  238.04 53.48 90 bottom
RI50  0_0402_5%  [R_0402-NPM]  237.15 53.48 90 bottom
RN37  10K_0402_5%  [R_0402]  24.55 15.2 270 top
RN99  0_0402_5%  [R0402_0OHM]  18.97 14.31 90 top
RN100  0_0402_5%  [R_0402]  28.24 14.36 90 top
RN101  0_0402_5%  [R_0402]  230.04 84.54 180 top
RPC1  33_0804_8P4R_5%  [RP_0804_8P4R]  174.05 57.17 90 top
RPC3  10K_8P4R_5%  [RP_0804_8P4R]  163.28 87.84 90 top
RPC4  10K_8P4R_5%  [RP_0804_8P4R]  170.11 87.78 90 top
RPC5  10K_8P4R_5%  [RP_0804_8P4R]  163.41 65.74 0 top
RPE7  10K_8P4R_5%  [RP_0804_8P4R]  248.71 31.58 90 bottom
RPE9  100K_0804_8P4R_5%  [RP_0804_8P4R]  266.4 50.48 270 top
RPE10  100K_0804_8P4R_5%  [RP_0804_8P4R]  257.59 42.19 270 top
RPE11  100K_0804_8P4R_5%  [RP_0804_8P4R]  258.78 45.33 270 top
RPE12  2.2K_0804_8P4R_5%  [RP_0804_8P4R]  261.76 45.33 270 top
RR3  10K_0402_5%  [R_0402]  276.23 62.63 270 top
RR4  6.2K_0402_1%  [R_0402]  274.08 55.68 0 top
RR5  0_0402_5%  [R0402_0OHM]  283.48 54.67 0 top
RR6  0_0402_5%  [R0402_0OHM]  283.48 55.62 0 top
RR7  0_0402_5%  [R0402_0OHM]  283.48 56.57 0 top
RR8  0_0402_5%  [R0402_0OHM]  283.48 57.52 0 top
RR9  0_0402_5%  [R0402_0OHM]  281.73 53.55 270 top
RR10  0_0402_5%  [R0402_0OHM]  282.62 53.55 270 top
RR20  0_0402_5%  [R0402_0OHM]  275.44 52.59 90 top
RR21  0_0402_5%  [R0402_0OHM]  276.34 52.59 90 top
RR22  10K_0402_5%  [R_0402]  275.35 62.63 270 top
RT1  3.3K_0402_5%  [R_0402]  40.15 81.47 0 bottom
RT2  2.2K_0402_5%  [R_0402]  41.78 70.87 270 bottom
RT3  2.2K_0402_5%  [R_0402]  40.89 70.87 270 bottom
RT4  3.3K_0402_5%  [R_0402]  40 70.87 270 bottom
RT5  10K_0402_5%  [R_0402]  36.62 65.03 90 top
RT6  10K_0402_5%  [R_0402]  34.84 64.73 0 top
RT7  10K_0402_5%  [R_0402]  36.19 63.59 180 top
RT8  10K_0402_5%  [R_0402]  37.51 65.03 90 top
RT9  0_0402_5%  [R0402_0OHM]  42.96 69.91 90 bottom
RT10  0_0402_5%  [R_0402]  41.94 82.37 270 bottom
RT11  10K_0402_5%  [R_0402]  30.4 65.49 180 top
RT12  2.2K_0402_5%  [R_0402]  39.43 69.05 0 bottom
RT13  2.2K_0402_5%  [R_0402]  39.92 67.27 0 bottom
RT14  2.2K_0402_5%  [R_0402]  37.59 62.06 0 top
RT15  2.2K_0402_5%  [R_0402]  34.84 65.67 90 top
RT16  10K_0402_5%  [R_0402]  29.76 67.78 0 bottom
RT17  10K_0402_5%  [R_0402]  32.17 63.92 90 top
RT18  2.2K_0402_5%  [R_0402]  37.51 67.52 90 bottom
RT19  2.2K_0402_5%  [R_0402]  38.4 67.52 90 bottom
RT20  10K_0402_5%  [R_0402]  31.28 65.69 0 top
RT21  1M_0402_5%  [R_0402]  28.49 65.49 90 top
RT22  1M_0201_5%  [R_0201]  26.08 71.24 270 top
RT23  100K_0402_5%  [R_0402]  33.06 63.84 90 top
RT24  100K_0402_5%  [R_0402]  39.92 63.2 0 bottom
RT25  100K_0402_5%  [R_0402]  31.27 66 90 bottom
RT26  100K_0402_5%  [R_0402]  29.76 63.08 90 top
RT27  10K_0402_5%  [R_0402]  31.28 63.92 90 top
RT28  100K_0402_5%  [R_0402]  37.46 66.65 0 bottom
RT29  100K_0402_5%  [R_0402]  39.39 60.79 90 top
RT30  1M_0402_5%  [R_0402]  39.92 64.6 0 bottom
RT31  1M_0402_5%  [R_0402]  28.87 63.71 90 top
RT32  1M_0402_5%  [R_0402]  29.18 61.55 0 top
RT33  100K_0402_5%  [R_0402]  37.51 40.73 0 bottom
RT34  3.01K_0402_1%  [R_0402]  34 56.44 270 top
RT35  14K_0402_1%~D  [R_0402]  33.83 61.52 180 top
RT36  100_0402_5%  [R_0402]  29.52 66 90 bottom
RT37  100_0402_5%  [R_0402]  39.92 62.32 0 bottom
RT38  14K_0402_1%  [R_0402]  35.98 55.66 270 top
RT39  4.75K_0402_0.5%  [R_0402]  31.82 62.19 180 top
RT40  0_0402_5%  [R0402_0OHM]  26.59 50.63 180 bottom
RT41  499_0201_1%  [R_0201]  31.45 54.31 180 top
RT42  499_0201_1%  [R_0201]  30.18 54.31 180 top
RT48  0_0603_5%  [R_0603]  24.87 81.62 0 top
RT49  0_0603_5%  [R_0603]  23.86 81.62 180 top
RT50  3.3K_0402_5%  [R_0402]  39.9 42.91 180 bottom
RT51  3.3K_0402_5%  [R_0402]  43.96 50.11 180 bottom
RT52  3.3K_0402_5%  [R_0402]  40.91 50.87 90 bottom
RT53  3.3K_0402_5%  [R_0402]  40.02 50.87 90 bottom
RT54  0_0402_5%  [R0402_0OHM]  44.06 48.12 180 bottom
RT55  0_0402_5%  [R0402_0OHM]  44.06 49.02 180 bottom
RT56  0_0402_5%  [R0402_0OHM]  41.7 51.79 270 bottom
RT57  0_0402_5%  [R0402_0OHM]  42.85 51.79 270 bottom
RT58  0_0402_5%  [R0402_0OHM]  37.63 87.62 180 top
RT59  0_0402_5%  [R0402_0OHM]  37.38 72.6 180 bottom
RT60  0_0402_5%  [R0402_0OHM]  37.63 85.72 180 top
RT63  0_0402_5%  [R_0402]  31.92 69.58 270 bottom
RT64  0_0402_5%  [R_0402]  36.49 75.27 0 bottom
RT65  0_0402_5%  [R_0402]  36.49 76.16 0 bottom
RT66  3.3K_0402_5%  [R_0402]  36.49 71.71 0 bottom
RT67  3.3K_0402_5%  [R_0402]  36.72 88.57 0 top
RT68  10K_0402_5%  [R_0402]  36.72 86.67 0 top
RT69  0_0402_5%  [R0402_0OHM]  35.65 69.24 270 bottom
RT70  0_0402_5%  [R0402_0OHM]  33.84 69.23 270 bottom
RT71  1M_0402_5%  [R_0402]  35.6 77.73 90 bottom
RT72  0_0402_5%  [R0402_0OHM]  30.14 77.68 90 bottom
RT73  0_0402_5%  [R0402_0OHM]  36.49 77.05 0 bottom
RT74  0_0402_5%  [R_0402]  33.82 77.73 90 bottom
RT75  0_0402_5%  [R_0402]  29.25 77.68 90 bottom
RT76  10K_0402_1%  [R_0402]  34 74.13 0 top
RT81  100K_0402_5%  [R_0402]  34.71 70.06 0 top
RT82  1M_0402_5%  [R_0402]  30.85 68.23 270 top
RT83  0_0402_5%  [R_0402]  31.86 68.23 270 top
RT84  0_0402_5%  [R_0402]  29.83 68.23 270 top
RT85  0_0402_5%  [R_0402]  28.81 68.23 270 top
RT86  1M_0402_5%  [R_0402]  34.71 77.73 90 bottom
RT87  0_0402_5%  [R0402_0OHM]  27.14 73.87 0 top
RT88  0_0402_5%  [R0402_0OHM]  24.99 76.67 0 top
RT89  0_0402_5%  [R_0402]  27.14 72.98 0 top
RT90  0_0402_5%  [R_0402]  24.99 75.78 0 top
RT92  0_0402_5%  [R0402_0OHM]  26.97 69.73 90 top
RT93  0_0402_5%  [R0402_0OHM]  27.86 69.73 90 top
RT95  100K_0201_5%  [R_0201]  25.4 71.08 0 bottom
RT96  100K_0201_5%  [R_0201]  25.4 70.19 0 bottom
RT97  0_0402_5%  [R_0402]  34.71 72.35 180 top
RT98  0_0402_5%  [R_0402]  33.82 73.24 0 top
RT99  0_0402_5%  [R0402_0OHM]  31.09 77.7 90 bottom
RT100  15K_0402_1%  [R_0402]  31.03 69.55 270 bottom
RT101  100K_0402_5%  [R_0402]  36.49 73.49 0 bottom
RT103  0_0402_5%  [R_0402]  25.82 77.81 180 top
RT104  0_0402_5%  [R0402_0OHM]  21.76 77.1 90 top
RT105  0_0402_5%  [R0402_0OHM]  24.12 78.57 180 bottom
RT106  10K_0402_5%  [R_0402]  36.49 69.94 0 bottom
RT107  10K_0402_5%  [R_0402]  36.49 70.82 0 bottom
RT108  0_0402_5%  [R0402_0OHM]  24.12 76.67 180 bottom
RT109  0_0402_5%  [R0402_0OHM]  25.89 75.62 180 bottom
RT110  0_0402_5%  [R_0402]  32.05 77.73 90 bottom
RT111  100K_0402_5%  [R_0402]  30.82 29.92 0 top
RT120  0_0402_5%  [R0402_0OHM]  15.49 83.52 180 top
RT121  0_0402_5%  [R0402_0OHM]  15.49 82.64 180 top
RT122  0_0402_5%  [R0402_0OHM]  15.08 83.52 0 bottom
RT123  0_0402_5%  [R0402_0OHM]  15.08 82.64 0 bottom
RT124  100K_0402_5%  [R_0402]  39.92 68.16 0 bottom
RT125  100K_0402_5%  [R_0402]  39.92 66.38 0 bottom
RT126  100K_0402_5%  [R_0402]  37.59 61.17 0 top
RT127  100K_0402_5%  [R_0402]  33.95 63.84 90 top
RT128  100K_0402_5%  [R_0402]  37.3 59.9 0 top
RT129  100K_0402_5%  [R_0402]  36.62 69.55 0 top
RT150  0_0402_5%  [R0402_0OHM]  27.14 38.57 0 top
RT151  0_0402_5%  [R0402_0OHM]  27.17 35.14 180 top
RT156  0_0402_5%  [R0402_0OHM]  30 36.36 90 top
RT159  0_0402_5%  [R0402_0OHM]  20.92 44.28 0 bottom
RT160  0_0402_5%  [R_0402]  28.92 39.5 270 bottom
RT161  0_0402_5%  [R_0402]  29.87 39.5 270 bottom
RT162  3.3K_0402_5%  [R_0402]  26.95 39.5 270 bottom
RT163  3.3K_0402_5%  [R_0402]  27.97 39.5 270 bottom
RT164  10K_0402_5%  [R_0402]  28.99 37.28 270 top
RT165  0_0402_5%  [R0402_0OHM]  21.89 41.61 180 bottom
RT166  0_0402_5%  [R0402_0OHM]  21.84 42.5 180 bottom
RT167  1M_0402_5%  [R_0402]  31.11 44.15 180 top
RT168  0_0402_5%  [R0402_0OHM]  35.6 43.39 0 bottom
RT169  0_0402_5%  [R0402_0OHM]  35.6 40.73 0 bottom
RT170  0_0402_5%  [R_0402]  35.6 41.61 0 bottom
RT171  0_0402_5%  [R_0402]  33.19 43.65 0 bottom
RT172  10K_0201_1%  [R_0201]  28.24 44.48 270 top
RT178  0_0402_5%  [R_0402]  32.88 69.11 90 top
RT180  0_0402_5%  [R_0402]  22.39 39.66 270 top
RT181  0_0402_5%  [R_0402]  21.46 39.71 180 top
RT182  1M_0402_5%  [R_0402]  31.06 45.47 90 top
RT183  0_0201_5%  [R0201_0OHM]  25.95 47.2 270 top
RT184  0_0201_5%  [R0201_0OHM]  27.35 43.42 90 top
RT185  0_0201_5%  [R_0201]  26.59 47.2 270 top
RT186  0_0201_5%  [R_0201]  26.46 43.42 90 top
RT188  0_0402_5%  [R0402_0OHM]  24.27 48.47 270 bottom
RT189  0_0402_5%  [R0402_0OHM]  24.93 37.12 270 top
RT191  0_0201_5%  [R_0201]  25.82 42 90 top
RT192  0_0201_5%  [R_0201]  25.19 42.63 180 top
RT193  0_0201_5%  [R0201_0OHM]  26.46 42.63 270 top
RT194  15K_0402_1%  [R_0402]  21.84 45.17 180 bottom
RT195  100K_0402_5%  [R_0402]  28.99 39.5 270 top
RT196  0_0402_5%  [R_0402]  32.81 48.09 90 bottom
RT197  0_0402_5%  [R0402_0OHM]  30 48.11 90 bottom
RT198  0_0402_5%  [R0402_0OHM]  31.03 48.12 90 bottom
RT199  10K_0402_5%  [R_0402]  23.28 39.66 270 top
RT200  10K_0402_5%  [R_0402]  24.17 39.66 270 top
RT201  0_0201_5%  [R0201_0OHM]  28.28 46.69 180 top
RT202  0_0402_5%  [R0402_0OHM]  29.05 48.11 90 bottom
RT203  0_0402_5%  [R_0402]  35.6 42.5 0 bottom
RT204  100K_0402_5%  [R_0402]  23.72 46.69 0 bottom
RT205  100K_0402_5%  [R_0402]  22.85 46.69 180 bottom
RT214  0_0402_5%  [R0402_0OHM]  15.49 68.54 180 top
RT215  0_0402_5%  [R0402_0OHM]  15.49 67.65 180 top
RT216  0_0402_5%  [R0402_0OHM]  15.08 68.54 0 bottom
RT217  0_0402_5%  [R0402_0OHM]  15.08 67.65 0 bottom
RT218  100K_0402_5%  [R_0402]  35.92 72.64 0 top
RT219  100K_0402_5%  [R_0402]  35.92 75.31 0 top
